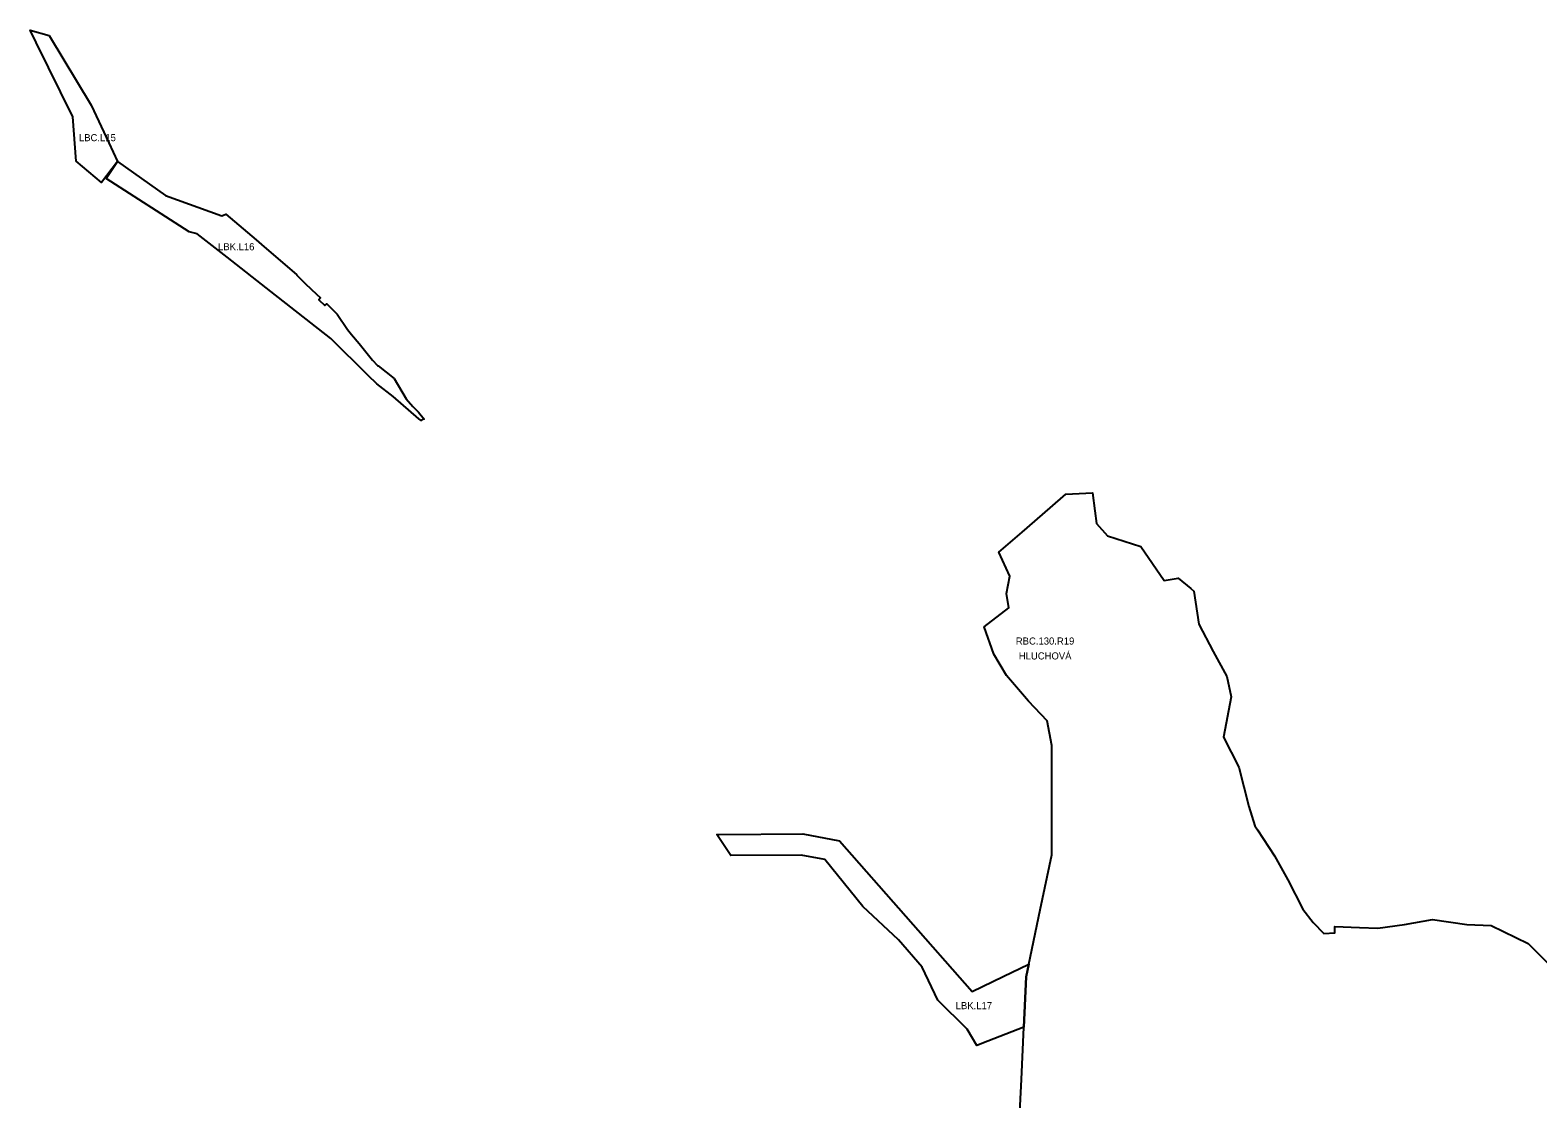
# Model space of a CAD drawing. Extents: x -450188 to -432919, y -1130252 to -1121189.
# Drawn here: x -437955 to -435829, y -1127067 to -1125559 of the extents above; entities that cross this region are included whole.
import ezdxf

# ---------------------------------------------------------------- set-up
doc = ezdxf.new("R2010")
doc.units = 0
for name, color, linetype in [('Vrstva 30', 7, 'Continuous'), ('Vrstva 32', 7, 'Continuous'), ('Vrstva 33', 7, 'Continuous'), ('Vrstva 36', 7, 'Continuous')]:
    doc.layers.add(name, color=color, linetype=linetype)

msp = doc.modelspace()

# ---------------------------------------------------------------- linework, layer by layer
at = {"layer": 'Vrstva 30'}
msp.add_line((-436550.6, -1126894.6), (-436546.8, -1126876.5), dxfattribs=at)
for points in [[(-436546.8, -1126876.5), (-436530.7, -1126799.9), (-436514.3, -1126722.3), (-436514.3, -1126687), (-436514.3, -1126568.1), (-436520.8, -1126533.3), (-436547.2, -1126505.7), (-436578.2, -1126469.7), (-436595.9, -1126439.4), (-436609.5, -1126401.1), (-436574.9, -1126373.9), (-436578.1, -1126353.9), (-436573.3, -1126329.4), (-436588.8, -1126295.6), (-436556.2, -1126267.3), (-436516.6, -1126233), (-436494.3, -1126213.8), (-436457, -1126211.7), (-436453.5, -1126237.3), (-436451.1, -1126255.2), (-436435.5, -1126272.6), (-436388.8, -1126287.5), (-436356, -1126335.5), (-436336.1, -1126332.4), (-436318.4, -1126347), (-436314.1, -1126350.5), (-436306.7, -1126397), (-436286.8, -1126435.6), (-436267.4, -1126470.7), (-436261.1, -1126499.5), (-436271.9, -1126556.4), (-436250.6, -1126599), (-436243.4, -1126626.5), (-436236.2, -1126654.1), (-436228, -1126681.3), (-436224.3, -1126687), (-436200.3, -1126723.8), (-436181.4, -1126757.8), (-436160.1, -1126799.2), (-436145.6, -1126818), (-436130.8, -1126833.2), (-436115, -1126832.2), (-436115, -1126823.7), (-436080.3, -1126824.9), (-436054.4, -1126825.8), (-436017, -1126820.8), (-435977.5, -1126813.8), (-435928.9, -1126820.8), (-435894.8, -1126821.9), (-435842.2, -1126847.6), (-435804.8, -1126885)], [(-435797.7, -1127801.8), (-436047.1, -1127584.1), (-436193.5, -1127539.8), (-436244.8, -1127584), (-436301.6, -1127633), (-436329.7, -1127657.1), (-436369.4, -1127691.4), (-436458.8, -1127576.8), (-436467.8, -1127507.6), (-436489.7, -1127342), (-436491.6, -1127327.6), (-436511.6, -1127176.5), (-436550.5, -1127132.4), (-436559.7, -1127094.2), (-436557.2, -1127039.4), (-436553.8, -1126965.3), (-436550.6, -1126894.6)]]:
    msp.add_lwpolyline(points, dxfattribs=at)
at = {"layer": 'Vrstva 32'}
msp.add_lwpolyline([(-437844.3, -1125718.1), (-437832, -1125744.4), (-437854.4, -1125774.2), (-437890.4, -1125744.1), (-437895, -1125681.4), (-437946.7, -1125576.6), (-437955.2, -1125559.4), (-437928.4, -1125566.7), (-437869.1, -1125665.1)], close=True, dxfattribs=at)
at = {"layer": 'Vrstva 33'}
for p, q in [((-437848, -1125768.5), (-437832, -1125744.4)), ((-437731.1, -1125843.9), (-437848, -1125768.5)), ((-436546.8, -1126876.5), (-436550.6, -1126894.6)), ((-436550.6, -1126894.6), (-436553.8, -1126965.7))]:
    msp.add_line(p, q, dxfattribs=at)
for points in [[(-437832, -1125744.4), (-437764.2, -1125792.8), (-437684.8, -1125821.2), (-437679.1, -1125818.8), (-437636.5, -1125855.2), (-437629, -1125861.6), (-437579.3, -1125904.5), (-437578.9, -1125905), (-437566.9, -1125917.1), (-437551.2, -1125931.9), (-437545.8, -1125937), (-437548.1, -1125939.5), (-437539.4, -1125947.7), (-437537, -1125945.2), (-437522.4, -1125959.9), (-437507.5, -1125981.5), (-437502.2, -1125988.6), (-437491, -1126001.5), (-437472.2, -1126024.9), (-437465.4, -1126032.3), (-437464.6, -1126033), (-437441.6, -1126050.7), (-437425, -1126079.1), (-437415.5, -1126090.2), (-437407.5, -1126097.9), (-437399.3, -1126107.8), (-437400.9, -1126107.6), (-437403.7, -1126110), (-437406.8, -1126107.3), (-437443, -1126076), (-437466.3, -1126058.1), (-437478.3, -1126046.3), (-437530.9, -1125994.2), (-437615.9, -1125927.9), (-437677.2, -1125879.7), (-437719.5, -1125846.5), (-437731.1, -1125843.9)], [(-436553.8, -1126965.7), (-436604.4, -1126985.3), (-436620.1, -1126991.5), (-436633.4, -1126968.2), (-436675, -1126927.2), (-436696.9, -1126880.7), (-436730.7, -1126842.3), (-436780.9, -1126795.2), (-436834.6, -1126729.1), (-436867.9, -1126722.7), (-436967.1, -1126723.6), (-436986.7, -1126693.8), (-436983.3, -1126693.7), (-436865.2, -1126692.6), (-436813.6, -1126702.6), (-436626.7, -1126915), (-436582.9, -1126893.9), (-436546.8, -1126876.5)]]:
    msp.add_lwpolyline(points, dxfattribs=at)

# ---------------------------------------------------------------- texts
at = {"layer": 'Vrstva 36'}
for s, p in [('LBC.L15', (-437886.4, -1125716)), ('LBK.L16', (-437690.2, -1125869.8)), ('RBC.130.R19', (-436565, -1126425.9)), ('HLUCHOVÁ', (-436560.8, -1126446.9)), ('LBK.L17', (-436649.8, -1126940.1))]:
    msp.add_text(s, height=10, dxfattribs=at).set_placement(p)

doc.saveas('drawing.dxf')
